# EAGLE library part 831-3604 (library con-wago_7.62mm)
Serie 831, Stiftleiste (für Leiterplatten) mit geraden Einlötstiften / Series 831, Male header (for PCBs) with straight solder pins Polzahl / Pole No.: 4 Bemessungsspannung / Rated Voltage: 630 V Nennstrom / Nominal Current: 41 A Lötstiftlänge: / Solder Pin Length: 4 mm Farbe / Color: lichtgrau / light gray Stand: 01.01.2012. Die jeweils aktuellen Daten zu diesem Artikel finden Sie in unserem Produktkatalog, den Sie unter www.wago.com einsehen können. As of: 01/01/2012. Please find the newest data for this article in our product catalogue, which can be viewed under www.wago.com.
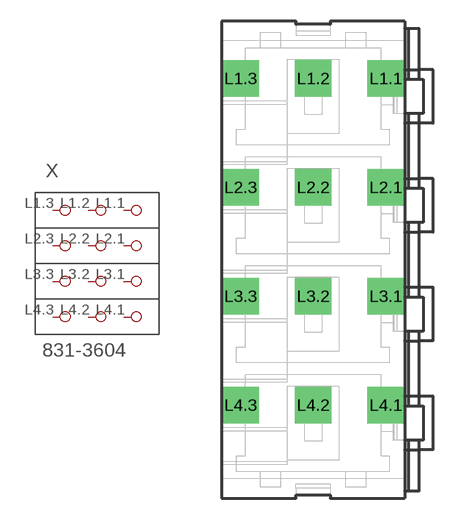
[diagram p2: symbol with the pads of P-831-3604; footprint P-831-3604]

Designator prefix X

## 831-3604  [P-831-3604]
L1.1  P1.1
L1.2  P1.2
L1.3  P1.3
L2.1  P2.1
L2.2  P2.2
L2.3  P2.3
L3.1  P3.1
L3.2  P3.2
L3.3  P3.3
L4.1  P4.1
L4.2  P4.2
L4.3  P4.3

## Footprint P-831-3604 (pad centres in mm)
drill 1.7 square: L1.1 4.08,12.7; L1.2 -1,12.7; L1.3 -6.08,12.7; L2.1 4.08,5.08; L2.2 -1,5.08; L2.3 -6.08,5.08; L3.1 4.08,-2.54; L3.2 -1,-2.54; L3.3 -6.08,-2.54; L4.1 4.08,-10.16; L4.2 -1,-10.16; L4.3 -6.08,-10.16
